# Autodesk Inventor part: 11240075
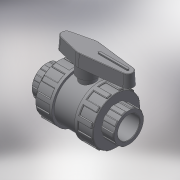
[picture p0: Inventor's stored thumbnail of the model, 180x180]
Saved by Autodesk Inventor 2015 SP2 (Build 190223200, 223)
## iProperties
Created: 2017-11
Part Number: 11240075
Material: Generic
Description: PLASSON BI STOP VALVE CEM PVC 75
Document SubType Name: Modeling
Designer: KIM
Density: 1 g/cm^3
Appearance: Default
Author: KIM
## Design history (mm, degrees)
derived "112400 - 112700.ipt"
feature "Solid1::112400 - 112700.ipt"
tag "TaggingFeature1"
body "Solid1"
other parameters: "d0" = 215, "d1" = 75, "d2" = 139, "d3" = 44, "d5" = 30.8, "d7" = 105, "d8" = 125.1, "d13" = 2.25, "d23" = 44, "d24" = 133.44, "d25" = 1.5, "d26" = 2.25, "d27" = 20.85, "d28" = 10.425, "d29" = 33, "d30" = 0, "d35" = 2.25, "d39" = 69.5, "d45" = 360 deg, "d47" = 1.5, "d50" = 76.45, "d51" = 41.7, "d53" = 0, "d55" = 15, "d56" = 7.5, "d57" = 30.8, "d58" = 0, "d59" = 2.25, "d61" = 360 deg, "d63" = 55.6, "d64" = 128, "d66" = 132, "d68" = 27.8, "d69" = 39.6, "d70" = 32, "d71" = 3 deg, "d73" = 2.78, "d74" = 52.8, "d75" = 3.84, "d76" = 0, "d77" = 1.5, "d_" = 75, "l_" = 44, "H_" = 215, "K_" = 139, "F_" = 128, "J_" = 132, "d67" = 55.6, "d72" = 13.9
